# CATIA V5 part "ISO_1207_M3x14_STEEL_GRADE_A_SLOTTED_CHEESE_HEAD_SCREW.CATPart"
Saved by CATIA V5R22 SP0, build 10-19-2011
Part number: ISO 1207 SCREW M3x14 STEEL GRADE A SLOTTED CHEESE HEAD
Publications: "Mating Face", "Axis"
Bounding box of the stored display mesh (mm): x -16 to 0, y -2.741 to 2.741, z -2.75 to 2.75
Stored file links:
  D:\PER\CAO_PER_MODIF_2025\CAO_PER_pick&place_2024P\Sous_Ensemble_Boite\ISO_1207_M3x14_STEEL_GRADE_A_SLOTTED_CHEESE_HEAD_SCREW.CATPart
  C:\Program Files\Dassault Systemes\B22\win_b64\startup\components\MechanicalStandardParts\EN_Standards\Design_Tables\EN_ISO_1207_GRADE_A_SLOTTED_CHEESE_HEAD_SCREW.txt
  C:\Program Files\Dassault Systemes\B22\win_b64\startup\components\MechanicalStandardParts\ISO_Standards\Design_Tables\ISO_1207_GRADE_A_SLOTTED_CHEESE_HEAD_SCREW.txt
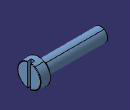
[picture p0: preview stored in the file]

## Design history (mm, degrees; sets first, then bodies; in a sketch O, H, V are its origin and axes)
Parameters
  d_dia = 3 mm
  dk_nom_head_dia = 5.5 mm
  k_max_head_depth = 2 mm
  n_nom_Slot_Width = 0.8 mm
  t_min_Slot_Depth = 0.85 mm
  r_min = 0.1 mm
  p_pitch = 0.5 mm
  Threading = 13 mm
  l_Length_nom = 14 mm
Body1 "PartBody" (main body)
  Sketch1 on zx-plane, origin (0, 0, 0), H (-1, 0, 0), V (0, 0, 1)
    line L1 (0, 0) -> (0, 2.575)
    line L2 (0, 2.575) -> (2, 2.75)
    point P2 (2, 2.75)
    line L3 (2, 2.75) -> (2, 1.4375)
    axis line L4 (-15.2845, 0) -> (155.0819, 0)
    reference intersected line E1 through (1000000, 0) direction (-1, 0) from xy-plane
    line L5 (2, 1.4375) -> (2.5, 1.4375)
    point P5 (3, 1.5)
    line L6 (3, 1.5) -> (16, 1.5)
    point P6 (16, 1.5)
    line L7 (16, 1.5) -> (16, 0)
    point P7 (16, 0)
    line L8 (3, 1.5) -> (2.5, 1.4375)
    point P9 (2.5, 1.4375)
    distance L1 P2 = 2 {= k_max_head_depth}
    distance P2 L4 = 2.75 {= dk_nom_head_dia /2}
    angle L4 L2 = 175
    length L7 = 1.5 {= d_dia /2}
    distance L5 L4 = 1.4375 {= (d_dia -(p_pitch/4))/2}
    distance P6 P5 = 13 {= Threading}
    distance L7 L1 = 16 {= l_Length_nom +k_max_head_depth}
    distance P9 P5 H = 0.5 {= p_pitch}
    vertical: L1 V, L3 V, L7 V
    horizontal: L4 H, L5 H
    coincidence: L4 E1, P7 L4
    parallelism: L6 L5
  Shaft1: profile Sketch1, axis Sketch1.L4, angle 360
  Fillet1: radius 0.1 {= r_min}, on edge [face of Shaft1 | face of Shaft1]
  Sketch2 on xy-plane, origin (0, 0, 0), H (1, 0, 0), V (0, 1, 0)
    line L1 (0, 0.4) -> (-0.85, 0.4)
    line L2 (-0.85, 0.4) -> (-0.85, -0.4)
    line L3 (-0.85, -0.4) -> (0, -0.4)
    line L4 (0, -0.4) -> (0, 0.4)
    distance O L2 = 0.85 {= t_min_Slot_Depth}
    distance H L1 = 0.4 {= n_nom_Slot_Width /2}
    distance H L3 = 0.4 {= n_nom_Slot_Width /2}
    vertical: L2 V
    coincidence: L4 V
  Pocket1: profile Sketch2, direction (0, 0, -1), through (limit type 3), opposite side length 20
  Fillet2: radius 0.1 {= r_min}, on edge [face of Shaft1 | face of Shaft1]
  Thread1: diameter 3 {= d_dia}, depth 13 {= Threading}, pitch 1, on face of Shaft1, from face of Shaft1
